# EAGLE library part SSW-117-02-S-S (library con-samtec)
THROUGH-HOLE .025" SQ POST SOCKET Source: Samtec SSW.pdf
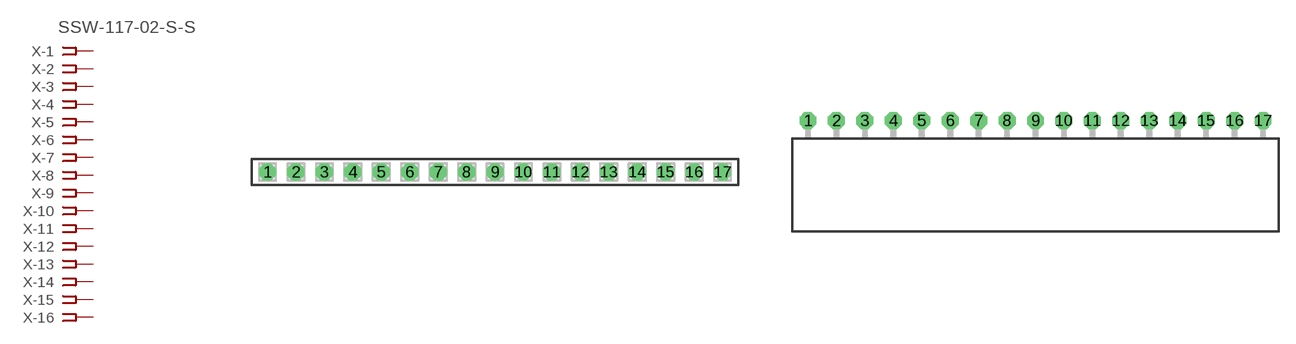
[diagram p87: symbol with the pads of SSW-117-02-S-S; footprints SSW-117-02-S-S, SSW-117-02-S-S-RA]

Designator prefix X; gates -1=FPINV -2=FPIN -3=FPIN -4=FPIN -5=FPIN -6=FPIN -7=FPIN -8=FPIN -9=FPIN -10=FPIN -11=FPIN -12=FPIN -13=FPIN -14=FPIN -15=FPIN -16=FPIN -17=FPIN

## SSW-117-02-S-S (MPN: SSW-117-02-S-S; OC_FARNELL: unknown; OC_NEWARK: 11P9592)  [SSW-117-02-S-S]
1  -1:1  pas
2  -2:1  pas
3  -3:1  pas
4  -4:1  pas
5  -5:1  pas
6  -6:1  pas
7  -7:1  pas
8  -8:1  pas
9  -9:1  pas
10  -10:1  pas
11  -11:1  pas
12  -12:1  pas
13  -13:1  pas
14  -14:1  pas
15  -15:1  pas
16  -16:1  pas
17  -17:1  pas

## SSW-117-02-S-S-RA (MPN: SSW-117-02-S-S-RA; OC_FARNELL: unknown; OC_NEWARK: 11P9593)  [SSW-117-02-S-S-RA]
Pads as for SSW-117-02-S-S

## Footprint SSW-117-02-S-S (pad centres in mm)
THROUGH-HOLE .025" SQ POST SOCKET Source: Samtec SSW.pdf
drill 1 pad 1.5 octagon: 1 -20.32,0; 2 -17.78,0; 3 -15.24,0; 4 -12.7,0; 5 -10.16,0; 6 -7.62,0; 7 -5.08,0; 8 -2.54,0; 9 0,0; 10 2.54,0; 11 5.08,0; 12 7.62,0; 13 10.16,0; 14 12.7,0; 15 15.24,0; 16 17.78,0; 17 20.32,0

## Footprint SSW-117-02-S-S-RA (pad centres in mm)
THROUGH-HOLE .025" SQ POST SOCKET Source: Samtec SSW.pdf
drill 1 pad 1.5 octagon: 1 -20.32,1.524; 2 -17.78,1.524; 3 -15.24,1.524; 4 -12.7,1.524; 5 -10.16,1.524; 6 -7.62,1.524; 7 -5.08,1.524; 8 -2.54,1.524; 9 0,1.524; 10 2.54,1.524; 11 5.08,1.524; 12 7.62,1.524; 13 10.16,1.524; 14 12.7,1.524; 15 15.24,1.524; 16 17.78,1.524; 17 20.32,1.524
